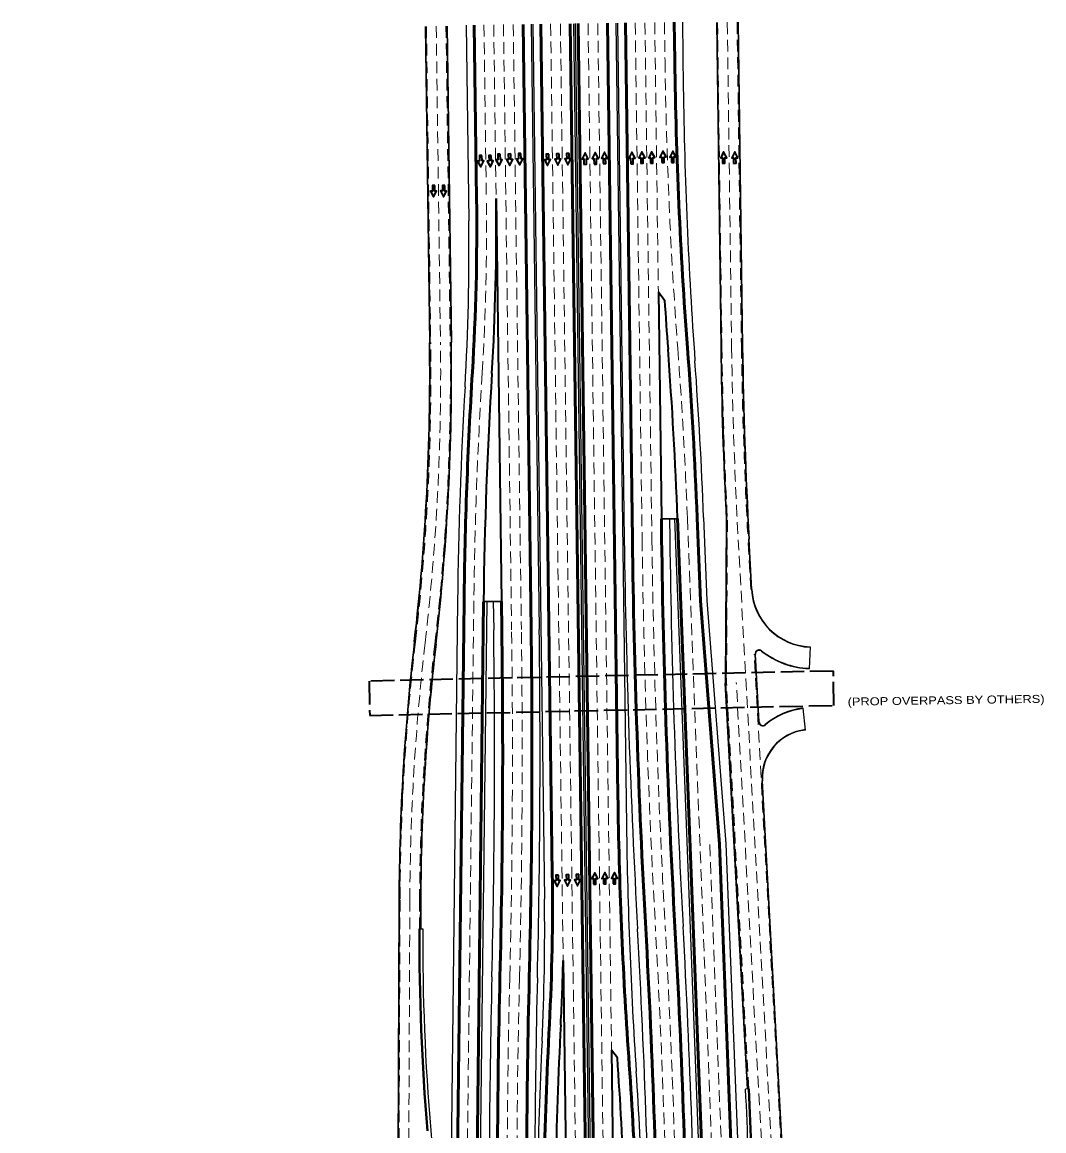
# Model space of a CAD drawing. Extents: x 2326434 to 2368642, y 6985225 to 6995090.
# Drawn here: x 2332670 to 2333927, y 6993727 to 6995090 of the extents above; entities that cross this region are included whole.
import ezdxf

# ---------------------------------------------------------------- set-up
doc = ezdxf.new("R2010")
doc.units = 0
doc.header["$LTSCALE"] = 4.8
doc.linetypes.add('LONG_DASHED', pattern=[7.5, 6, -1.5])
doc.linetypes.add('MEDIUM_DASHED', pattern=[4.5, 3, -1.5])
for name, color, linetype, lineweight in [('10', 7, 'Continuous', 35), ('11', 7, 'Continuous', 35), ('20', 7, 'LONG_DASHED', 35), ('26', 7, 'Continuous', 25), ('27', 7, 'Continuous', 25), ('28', 7, 'Continuous', 25), ('30', 7, 'Continuous', 25), ('40', 7, 'Continuous', 35), ('50', 7, 'MEDIUM_DASHED', 13)]:
    doc.layers.add(name, color=color, linetype=linetype, lineweight=lineweight)

msp = doc.modelspace()

# ---------------------------------------------------------------- linework, layer by layer
at = {"layer": '10'}
for p, q in [((2333253.137, 6994873.193), (2333259.765, 6994377.566)), ((2333452.688, 6994758.564), (2333460.359, 6994748.247)), ((2333452.688, 6994758.564), (2333456.421, 6994479.402)), ((2333259.766, 6994377.537), (2333237.768, 6994377.243)), ((2333335.676, 6993936.117), (2333341.676, 6993487.504)), ((2333395.156, 6993825.808), (2333399.564, 6993496.246)), ((2333402.303, 6993816.543), (2333395.157, 6993825.808))]:
    msp.add_line(p, q, dxfattribs=at)
for centre, radius, start, end in [((2330364.606, 6994834.542), 2888.789, 356.50065, 0.76624), ((2338942.949, 6994309.966), 5705.578, 176.50065, 179.32439), ((2331921.237, 6992748.984), 1265.239, 273.05017, 273.05017), ((2330457.709, 6994004.927), 2878.789, 357.05736, 358.63038), ((2339040.744, 6993563.724), 5715.578, 177.05736, 180.76624), ((2327700.496, 6993420.026), 5715.578, 0.76624, 3.97808)]:
    msp.add_arc(centre, radius, start, end, dxfattribs=at)
at = {"layer": '11'}
msp.add_line((2333456.421, 6994479.402), (2333476.419, 6994479.669), dxfattribs=at)
for centre, radius, start, end in [((2339201.955, 6995119.38), 5753.578, 183.69842, 184.30136), ((2327775.075, 6994259.917), 5705.578, 2.20731, 4.30136)]:
    msp.add_arc(centre, radius, start, end, dxfattribs=at)
at = {"layer": '20'}
msp.add_lwpolyline([(2333667.959, 6994292.09), (2333097.206, 6994279.743), (2333097.771, 6994237.554), (2333668.523, 6994249.877)], close=True, dxfattribs=at)
at = {"layer": '26'}
for p, q in [((2333216.281, 6995086.502), (2333219.503, 6994845.602)), ((2333296.274, 6995087.572), (2333306.227, 6994343.337)), ((2333402.264, 6995088.989), (2333410.76, 6994453.734)), ((2333482.257, 6995090.059), (2333483.328, 6995009.976)), ((2333466.42, 6994479.536), (2333466.755, 6994454.483)), ((2333249.767, 6994377.403), (2333250.232, 6994342.588))]:
    msp.add_line(p, q, dxfattribs=at)
at = {"layer": '26', "lineweight": 53}
for p, q in [((2333226.28, 6995086.636), (2333229.139, 6994872.853)), ((2333286.275, 6995087.438), (2333296.228, 6994343.203)), ((2333412.263, 6995089.123), (2333420.759, 6994453.868)), ((2333472.258, 6995089.925), (2333472.889, 6995042.759)), ((2333456.421, 6994479.402), (2333456.756, 6994454.349)), ((2333259.766, 6994377.537), (2333260.232, 6994342.721))]:
    msp.add_line(p, q, dxfattribs=at)
at = {"layer": '26'}
for centre, radius, start, end in [((2344878.891, 6994607.111), 11469.156, 180.76624, 183.16007), ((2344878.891, 6994607.111), 11413.156, 180.76624, 183.16007), ((2321838.097, 6994189.96), 11413.156, 358.62517, 0.76624), ((2321838.097, 6994189.96), 11469.156, 358.62517, 0.76624), ((2321995.428, 6993343.725), 11449.156, 0.76624, 3.16007), ((2321995.428, 6993343.725), 11505.156, 0.76624, 3.16007), ((2344749.811, 6993640.078), 11505.156, 178.62517, 180.76624), ((2344749.811, 6993640.078), 11449.156, 178.62517, 180.76624)]:
    msp.add_arc(centre, radius, start, end, dxfattribs=at)
at = {"layer": '26', "lineweight": 53}
for centre, radius, start, end in [((2344878.891, 6994607.111), 11459.156, 180.76624, 183.16007), ((2344878.891, 6994607.111), 11423.156, 180.76624, 183.16007), ((2321838.097, 6994189.96), 11423.156, 358.62517, 0.76624), ((2321838.097, 6994189.96), 11459.156, 358.62517, 0.76624), ((2321995.428, 6993343.725), 11459.156, 0.76624, 3.16007), ((2321995.428, 6993343.725), 11495.156, 0.76624, 3.16007), ((2344749.811, 6993640.078), 11495.156, 178.62517, 180.76624), ((2344749.811, 6993640.078), 11459.156, 178.62517, 180.76624)]:
    msp.add_arc(centre, radius, start, end, dxfattribs=at)
at = {"layer": '27'}
for p, q in [((2333472.419, 6994479.616), (2333566.28, 6992044.449)), ((2333508.396, 6994480.902), (2333512.335, 6994378.687)), ((2333205.77, 6994377.62), (2333186.389, 6992734.065)), ((2333241.769, 6994377.296), (2333224.033, 6992873.304)), ((2333512.335, 6994378.687), (2333535.881, 6994079.372)), ((2333535.881, 6994079.372), (2333568.465, 6993233.999)), ((2333158.938, 6993975.08), (2333162.938, 6993975.064)), ((2333563.892, 6993778.088), (2333559.898, 6993777.869)), ((2333172.758, 6993726.908), (2333194.957, 6993460.668))]:
    msp.add_line(p, q, dxfattribs=at)
at = {"layer": '27', "lineweight": 53}
for p, q in [((2333476.419, 6994479.669), (2333570.277, 6992044.603)), ((2333500.402, 6994480.594), (2333504.341, 6994378.379)), ((2333213.77, 6994377.526), (2333194.388, 6992733.971)), ((2333237.768, 6994377.243), (2333220.034, 6992873.351)), ((2333527.887, 6994079.064), (2333504.341, 6994378.379)), ((2333560.471, 6993233.691), (2333527.887, 6994079.064))]:
    msp.add_line(p, q, dxfattribs=at)
for centre, radius, start, end in [((2339201.955, 6995119.38), 5729.578, 180.76624, 184.30136), ((2330364.606, 6994834.542), 2864.789, 356.50065, 0.76624), ((2327775.075, 6994259.917), 5729.578, 2.20731, 4.30136), ((2338942.949, 6994309.966), 5729.578, 176.50065, 179.32439)]:
    msp.add_arc(centre, radius, start, end, dxfattribs=at)
at = {"layer": '27'}
for centre, radius, start, end in [((2339212.394, 6995086.598), 5729.578, 180.76624, 184.13411), ((2330354.97, 6994807.291), 2864.789, 356.68574, 0.76624), ((2327775.075, 6994259.917), 5737.578, 2.20731, 4.13411), ((2338942.949, 6994309.966), 5737.578, 176.68574, 179.32439), ((2336009.703, 6993963.449), 2846.789, 179.76624, 184.76624), ((2330717.37, 6993622.159), 2846.789, 356.76624, 3.13545)]:
    msp.add_arc(centre, radius, start, end, dxfattribs=at)
at = {"layer": '27', "lineweight": 40}
for centre, start, end in [((2336009.703, 6993963.449), 179.76624, 184.76624), ((2330717.37, 6993622.159), 356.76624, 3.13545)]:
    msp.add_arc(centre, 2850.789, start, end, dxfattribs=at)
at = {"layer": '28'}
for p, q in [((2333166.047, 6995084.974), (2333171.253, 6994695.681)), ((2333166.547, 6995084.981), (2333171.753, 6994695.688)), ((2333192.544, 6995085.328), (2333197.751, 6994696.035)), ((2333193.044, 6995085.335), (2333198.251, 6994696.042)), ((2333524.007, 6995089.761), (2333529.344, 6994690.702)), ((2333524.507, 6995089.768), (2333529.844, 6994690.709)), ((2333550.504, 6995090.116), (2333555.841, 6994691.056)), ((2333551.004, 6995090.122), (2333556.341, 6994691.063)), ((2333536.142, 6994477.624), (2333535.053, 6994277.122)), ((2333536.642, 6994477.621), (2333535.552, 6994277.15)), ((2333567.304, 6994392.262), (2333563.906, 6994454.288)), ((2333567.803, 6994392.29), (2333564.405, 6994454.316)), ((2333639.262, 6994321.922), (2333638.2, 6994294.943)), ((2333576.222, 6994229.461), (2333571.658, 6994312.782)), ((2333576.721, 6994229.488), (2333572.157, 6994312.81)), ((2333562.394, 6993778.006), (2333535.053, 6994277.122)), ((2333562.893, 6993778.033), (2333535.552, 6994277.15)), ((2333633.665, 6994219.504), (2333630.746, 6994246.346)), ((2333639.033, 6993082.825), (2333580.187, 6994157.071)), ((2333639.532, 6993082.852), (2333580.686, 6994157.099)), ((2333133.583, 6994010.708), (2333129.307, 6992962.642)), ((2333134.083, 6994010.706), (2333129.807, 6992962.64)), ((2333160.083, 6994010.6), (2333159.938, 6993975.068)), ((2333160.583, 6994010.598), (2333160.438, 6993975.066))]:
    msp.add_line(p, q, dxfattribs=at)
for centre, radius, start, end in [((2330307.22, 6994657.377), 2864.289, 353.40183, 0.76624), ((2330307.22, 6994657.377), 2864.789, 353.40183, 0.76624), ((2330307.22, 6994657.377), 2890.789, 353.40183, 0.76624), ((2330307.22, 6994657.377), 2891.289, 353.40183, 0.76624), ((2339284.907, 6994767.677), 5756.078, 180.76623, 182.8884), ((2339284.907, 6994767.677), 5755.578, 180.76623, 182.8884), ((2339284.907, 6994767.677), 5729.578, 180.76623, 183.13545), ((2339284.907, 6994767.677), 5729.078, 180.76623, 183.13545), ((2333642.191, 6994396.364), 75, 183.13545, 267.74632), ((2333642.191, 6994396.364), 74.5, 183.13545, 267.74632), ((2335998.848, 6993999.018), 2865.289, 173.40183, 179.76624), ((2335998.848, 6993999.018), 2864.789, 173.40183, 179.76624), ((2335998.848, 6993999.018), 2838.789, 173.40183, 179.76624), ((2335998.848, 6993999.018), 2838.289, 173.40183, 179.76624), ((2333576.65, 6994313.056), 5, 51.80679, 183.13545), ((2333576.65, 6994313.056), 4.5, 51.80679, 183.13545), ((2333642.191, 6994396.364), 101.5, 231.80679, 267.74632), ((2333642.191, 6994396.364), 101, 231.80679, 267.74632), ((2333640.097, 6994160.353), 86.5, 96.20633, 130.32081), ((2333640.097, 6994160.353), 86, 96.20633, 130.32081), ((2333581.214, 6994229.734), 5, 183.13545, 310.32081), ((2333581.214, 6994229.734), 4.5, 183.13545, 310.32081), ((2333640.097, 6994160.353), 60, 96.20633, 183.13545), ((2333640.097, 6994160.353), 59.5, 96.20633, 183.13545)]:
    msp.add_arc(centre, radius, start, end, dxfattribs=at)
at = {"layer": '30'}
for p, q in [((2333298.274, 6995087.599), (2333312.664, 6994011.586)), ((2333348.269, 6995088.267), (2333387.943, 6992121.787)), ((2333350.269, 6995088.294), (2333389.943, 6992121.813)), ((2333400.265, 6995088.963), (2333413.464, 6994102.038))]:
    msp.add_line(p, q, dxfattribs=at)
at = {"layer": '30', "lineweight": 53}
for p, q in [((2333308.273, 6995087.732), (2333322.242, 6994043.237)), ((2333344.27, 6995088.214), (2333383.944, 6992121.733)), ((2333354.269, 6995088.347), (2333393.943, 6992121.867)), ((2333390.265, 6995088.829), (2333402.977, 6994138.382))]:
    msp.add_line(p, q, dxfattribs=at)
for centre, radius, start, end in [((2339132.043, 6994215.003), 5729.578, 180.76624, 183.97808), ((2330457.709, 6994004.927), 2864.789, 357.05736, 0.76624), ((2339040.744, 6993563.724), 5729.578, 177.05736, 180.76624), ((2327700.496, 6993420.026), 5729.578, 0.76624, 3.97808)]:
    msp.add_arc(centre, radius, start, end, dxfattribs=at)
at = {"layer": '30'}
for centre, radius, start, end in [((2339142.53, 6994178.66), 5729.578, 180.76624, 183.79329), ((2330448.132, 6993973.275), 2864.789, 357.27117, 0.76624), ((2339040.744, 6993563.724), 5737.578, 177.27117, 180.76624), ((2327700.496, 6993420.026), 5737.578, 0.76624, 3.79329)]:
    msp.add_arc(centre, radius, start, end, dxfattribs=at)
at = {"layer": '40'}
for points in [[(2333271.175, 6994928.074), (2333268.177, 6994927.955), (2333268.445, 6994921.154), (2333266.01, 6994921.058), (2333270.069, 6994914.012), (2333273.561, 6994921.356), (2333271.443, 6994921.272)], [(2333283.528, 6994928.799), (2333280.53, 6994928.681), (2333280.798, 6994921.879), (2333278.363, 6994921.783), (2333282.422, 6994914.738), (2333285.914, 6994922.081), (2333283.796, 6994921.998)], [(2333330.582, 6994928.348), (2333327.582, 6994928.301), (2333327.689, 6994921.495), (2333325.252, 6994921.457), (2333329.143, 6994914.317), (2333332.808, 6994921.576), (2333330.689, 6994921.542)], [(2333342.949, 6994928.78), (2333339.949, 6994928.733), (2333340.055, 6994921.927), (2333337.618, 6994921.889), (2333341.51, 6994914.749), (2333345.175, 6994922.008), (2333343.056, 6994921.974)], [(2333361.229, 6994915.25), (2333364.23, 6994915.283), (2333364.154, 6994922.089), (2333366.591, 6994922.116), (2333362.732, 6994929.274), (2333359.034, 6994922.032), (2333361.153, 6994922.056)], [(2333373.598, 6994915.625), (2333376.598, 6994915.659), (2333376.522, 6994922.465), (2333378.96, 6994922.492), (2333375.101, 6994929.65), (2333371.402, 6994922.408), (2333373.522, 6994922.431)], [(2333384.919, 6994916.164), (2333387.92, 6994916.198), (2333387.844, 6994923.004), (2333390.281, 6994923.031), (2333386.423, 6994930.189), (2333382.724, 6994922.947), (2333384.844, 6994922.971)], [(2333418.765, 6994916.007), (2333421.765, 6994916.064), (2333421.636, 6994922.87), (2333424.073, 6994922.916), (2333420.158, 6994930.043), (2333416.517, 6994922.772), (2333418.636, 6994922.813)], [(2333431.13, 6994916.48), (2333434.131, 6994916.537), (2333434.002, 6994923.342), (2333436.438, 6994923.388), (2333432.524, 6994930.515), (2333428.882, 6994923.245), (2333431.001, 6994923.285)], [(2333443.042, 6994916.592), (2333446.042, 6994916.649), (2333445.913, 6994923.454), (2333448.35, 6994923.5), (2333444.435, 6994930.628), (2333440.794, 6994923.357), (2333442.913, 6994923.397)], [(2333456.935, 6994917.406), (2333459.935, 6994917.463), (2333459.806, 6994924.268), (2333462.243, 6994924.315), (2333458.328, 6994931.442), (2333454.687, 6994924.171), (2333456.806, 6994924.211)], [(2333468.939, 6994917.512), (2333471.939, 6994917.569), (2333471.81, 6994924.374), (2333474.247, 6994924.42), (2333470.332, 6994931.548), (2333466.691, 6994924.277), (2333468.81, 6994924.317)], [(2333531.598, 6994916.479), (2333534.598, 6994916.536), (2333534.469, 6994923.341), (2333536.906, 6994923.388), (2333532.991, 6994930.515), (2333529.35, 6994923.244), (2333531.469, 6994923.284)], [(2333545.293, 6994916.479), (2333548.294, 6994916.536), (2333548.165, 6994923.341), (2333550.601, 6994923.388), (2333546.687, 6994930.515), (2333543.045, 6994923.244), (2333545.164, 6994923.284)], [(2333235.575, 6994926.345), (2333232.577, 6994926.227), (2333232.845, 6994919.425), (2333230.41, 6994919.329), (2333234.469, 6994912.284), (2333237.961, 6994919.627), (2333235.843, 6994919.544)], [(2333247.237, 6994926.345), (2333244.239, 6994926.227), (2333244.507, 6994919.425), (2333242.072, 6994919.329), (2333246.132, 6994912.284), (2333249.624, 6994919.627), (2333247.506, 6994919.544)], [(2333258.214, 6994927.718), (2333255.215, 6994927.599), (2333255.484, 6994920.798), (2333253.048, 6994920.702), (2333257.108, 6994913.656), (2333260.6, 6994921), (2333258.482, 6994920.916)], [(2333317.913, 6994927.809), (2333314.912, 6994927.762), (2333315.019, 6994920.956), (2333312.582, 6994920.918), (2333316.474, 6994913.778), (2333320.139, 6994921.036), (2333318.02, 6994921.003)], [(2333177.882, 6994889.167), (2333174.881, 6994889.204), (2333174.798, 6994882.398), (2333172.36, 6994882.428), (2333176.05, 6994875.182), (2333179.917, 6994882.335), (2333177.798, 6994882.361)], [(2333190.256, 6994889.253), (2333187.255, 6994889.29), (2333187.172, 6994882.484), (2333184.734, 6994882.514), (2333188.424, 6994875.267), (2333192.291, 6994882.421), (2333190.172, 6994882.447)], [(2333342.441, 6994041.65), (2333339.441, 6994041.603), (2333339.548, 6994034.797), (2333337.111, 6994034.759), (2333341.002, 6994027.619), (2333344.667, 6994034.877), (2333342.548, 6994034.844)], [(2333354.808, 6994042.082), (2333351.807, 6994042.035), (2333351.914, 6994035.229), (2333349.477, 6994035.191), (2333353.369, 6994028.051), (2333357.034, 6994035.309), (2333354.915, 6994035.276)], [(2333372.928, 6994029.953), (2333375.929, 6994029.987), (2333375.853, 6994036.793), (2333378.29, 6994036.82), (2333374.431, 6994043.978), (2333370.733, 6994036.736), (2333372.852, 6994036.76)], [(2333385.297, 6994030.329), (2333388.297, 6994030.362), (2333388.221, 6994037.168), (2333390.659, 6994037.196), (2333386.8, 6994044.353), (2333383.101, 6994037.111), (2333385.221, 6994037.135)], [(2333397.209, 6994030.347), (2333400.209, 6994030.381), (2333400.134, 6994037.187), (2333402.571, 6994037.214), (2333398.712, 6994044.372), (2333395.014, 6994037.13), (2333397.133, 6994037.154)], [(2333329.772, 6994041.11), (2333326.771, 6994041.063), (2333326.878, 6994034.257), (2333324.441, 6994034.219), (2333328.332, 6994027.079), (2333331.998, 6994034.338), (2333329.878, 6994034.305)]]:
    msp.add_lwpolyline(points, close=True, dxfattribs=at)
at = {"layer": '50'}
for p, q in [((2333167.547, 6995084.994), (2333172.753, 6994695.701)), ((2333179.546, 6995085.154), (2333184.752, 6994695.861)), ((2333191.544, 6995085.315), (2333196.751, 6994696.022)), ((2333238.279, 6995086.796), (2333241.138, 6994873.013)), ((2333250.278, 6995086.957), (2333253.137, 6994873.193)), ((2333262.277, 6995087.117), (2333272.23, 6994342.882)), ((2333274.276, 6995087.278), (2333284.229, 6994343.042)), ((2333320.272, 6995087.893), (2333335.676, 6993936.117)), ((2333332.271, 6995088.053), (2333371.945, 6992121.573)), ((2333366.268, 6995088.508), (2333405.942, 6992122.027)), ((2333378.267, 6995088.668), (2333395.156, 6993825.808)), ((2333424.262, 6995089.284), (2333432.758, 6994454.028)), ((2333436.261, 6995089.444), (2333444.757, 6994454.189)), ((2333448.26, 6995089.604), (2333452.688, 6994758.564)), ((2333460.259, 6995089.765), (2333460.89, 6995042.598)), ((2333525.507, 6995089.781), (2333530.844, 6994690.722)), ((2333537.505, 6995089.942), (2333542.842, 6994690.882)), ((2333549.504, 6995090.102), (2333554.841, 6994691.043)), ((2333488.411, 6994480.132), (2333582.268, 6992045.065)), ((2333537.642, 6994477.615), (2333536.551, 6994277.204)), ((2333626.052, 6993082.114), (2333550.926, 6994453.577)), ((2333566.305, 6994392.207), (2333562.908, 6994454.234)), ((2333225.769, 6994377.384), (2333206.387, 6992733.829)), ((2333638.034, 6993082.77), (2333570.659, 6994312.728)), ((2333563.892, 6993778.088), (2333536.551, 6994277.204)), ((2333581.728, 6993671.876), (2333548.526, 6994277.996)), ((2333515.896, 6994078.601), (2333552.612, 6993126.018)), ((2333135.083, 6994010.702), (2333130.807, 6992962.636)), ((2333147.083, 6994010.653), (2333142.807, 6992962.587)), ((2333159.083, 6994010.604), (2333158.938, 6993975.072))]:
    msp.add_line(p, q, dxfattribs=at)
for centre, radius, start, end in [((2339201.955, 6995119.38), 5741.578, 180.76624, 184.30136), ((2330364.606, 6994834.542), 2876.789, 356.50065, 0.76624), ((2330307.22, 6994657.377), 2865.789, 353.40183, 0.76624), ((2330307.22, 6994657.377), 2877.789, 353.40183, 0.76624), ((2330307.22, 6994657.377), 2889.789, 353.40183, 0.76624), ((2327775.075, 6994259.917), 5717.578, 2.20731, 4.30136), ((2339284.907, 6994767.677), 5754.578, 180.76623, 182.8884), ((2339284.907, 6994767.677), 5742.578, 180.76623, 183.13545), ((2339284.907, 6994767.677), 5730.578, 180.76623, 183.13545), ((2338942.949, 6994309.966), 5717.578, 176.50065, 179.32439), ((2344878.891, 6994607.111), 11447.156, 180.76624, 183.16007), ((2344878.891, 6994607.111), 11435.156, 180.76624, 183.16007), ((2321838.097, 6994189.96), 11435.156, 358.62517, 0.76624), ((2321838.097, 6994189.96), 11447.156, 358.62517, 0.76624), ((2335998.848, 6993999.018), 2863.789, 173.40183, 179.76624), ((2335998.848, 6993999.018), 2851.789, 173.40183, 179.76624), ((2335998.848, 6993999.018), 2839.789, 173.40183, 179.76624), ((2321995.428, 6993343.725), 11471.156, 0.76624, 3.16007), ((2321995.428, 6993343.725), 11483.156, 0.76624, 3.16007), ((2344749.811, 6993640.078), 11483.156, 178.62517, 180.76624), ((2344749.811, 6993640.078), 11471.156, 178.62517, 180.76624)]:
    msp.add_arc(centre, radius, start, end, dxfattribs=at)

# ---------------------------------------------------------------- texts
at = {"layer": '10', "width": 1.2}
msp.add_text('(PROP OVERPASS BY OTHERS)', height=9.843, rotation=0.841, dxfattribs=at).set_placement((2333685.526, 6994249.474))

doc.saveas('drawing.dxf')
